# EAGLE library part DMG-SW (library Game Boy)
DMG Power Switch Pins 1 and 2 are only connected when the power is ON, pins 3 and 4 are only connected when the power is OFF.
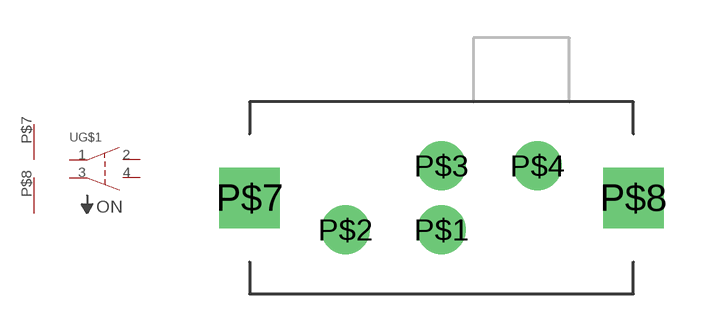
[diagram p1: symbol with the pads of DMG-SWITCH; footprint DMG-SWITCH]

Designator prefix -; gates G$1=DMG-SW G$2=PWRGND G$3=PWRGND

## DMG-SW  [DMG-SWITCH]
P$1  G$1:1
P$2  G$1:2
P$3  G$1:3
P$4  G$1:4
P$7  G$2:GND  pwr
P$8  G$3:GND  pwr

## Footprint DMG-SWITCH (pad centres in mm)
drill 0.8 pad 1.93 round: P$1 0,-1.27; P$2 -3.81,-1.27; P$3 0,1.27; P$4 3.81,1.27
drill 1.6 square: P$7 -7.62,0; P$8 7.62,0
